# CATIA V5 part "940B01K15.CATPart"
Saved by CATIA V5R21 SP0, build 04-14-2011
Part number: 940B01K15
Bounding box of the stored display mesh (mm): x -8.5 to 406.7, y -7 to 7, z -25.901 to 9.099
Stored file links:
  C:\Users\ALI OZGUN\Desktop\alhan\940B01K15.CATPart
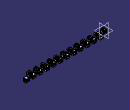
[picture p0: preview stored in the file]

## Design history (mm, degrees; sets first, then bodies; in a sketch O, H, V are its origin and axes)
Body1 (main body)
  Sketch1 on zx-plane, origin (0, 0, 0), H (-1, 0, 0), V (0, 0, 1)
    point P1 (-8.5, -8.9006)
    line L1 (-8.5, -7.9006) -> (-8, -7.4006)
    point P2 (-8, -7.4006)
    line L2 (-8, -7.4006) -> (-8, 6.6246)
    point P3 (-8, 6.6246)
    line L3 (-8, 6.6246) -> (-5.5251, 9.0994)
    point P4 (-5.5251, 9.0994)
    line L4 (-5.5251, 9.0994) -> (0, 9.0994)
    point P5 (0, 9.0994)
    line L5 (-8.5, -7.9006) -> (-8.5, -11.9006)
    point P6 (-8.5, -11.9006)
    line L6 (-8.5, -11.9006) -> (-5, -8.4006)
    point P7 (-3.5, -6.9006)
    line L7 (-5, -6.9006) -> (0, -6.9006)
    point P8 (0, -6.9006)
    line L8 (0, 6.2994) -> (-4.0825, 6.2994)
    point P9 (-4.0825, 6.2994)
    line L9 (-4.0825, 6.2994) -> (-5.2, 5.1819)
    point P10 (-5.2, 5.1819)
    line L10 (-5.2, 5.1819) -> (-5.2, -3.4006)
    point P11 (-5.2, -3.4006)
    line L11 (-5.2, -3.4006) -> (0, -3.4006)
    point P12 (0, -3.4006)
    point P13 (-8.5, -7.9006)
    point P14 (8, -7.4006)
    point P15 (8.5, -7.9006)
    line L12 (8.5, -7.9006) -> (8, -7.4006)
    point P16 (8, 6.6246)
    line L13 (8, -7.4006) -> (8, 6.6246)
    point P17 (5.5251, 9.0994)
    line L14 (8, 6.6246) -> (5.5251, 9.0994)
    point P18 (8.5, -11.9006)
    line L15 (8.5, -7.9006) -> (8.5, -11.9006)
    point P19 (3.5, -6.9006)
    line L16 (8.5, -11.9006) -> (5, -8.4006)
    point P20 (5.2, 5.1819)
    point P21 (4.0825, 6.2994)
    line L17 (4.0825, 6.2994) -> (5.2, 5.1819)
    point P22 (5.2, -3.4006)
    line L18 (5.2, 5.1819) -> (5.2, -3.4006)
    point P23 (0, -6.9006)
    line L19 (5, -6.9006) -> (0, -6.9006)
    point P24 (0, -3.4006)
    line L20 (5.2, -3.4006) -> (0, -3.4006)
    line L21 (0, 6.2994) -> (4.0825, 6.2994)
    point P25 (0, 9.0994)
    line L22 (5.5251, 9.0994) -> (0, 9.0994)
    point P26 (0, 6.2994)
    point P27 (0, 6.2994)
    line L23 (-5, -6.9006) -> (-5, -8.4006)
    line L24 (5, -6.9006) -> (5, -8.4006)
    distance L2 V = 8
    angle L3 L2 = 135
    distance L4 H = 9.0994
    distance L8 L4 = 2.8
    distance L10 L2 = 2.8
    distance L11 L7 = 3.5
    distance L9 L3 = 3
    length L3 = 3.5
    distance L4 L7 = 16
    distance L4 P6 = 21
    distance L5 L2 = 0.5
    length L5 = 4
    distance L23 L2 = 3
    vertical: L2 V, L5 V, L10 V, L23 V
    parallelism: L3 L1, L6 L1
    horizontal: L4 H, L7 H, L8 H, L11 H
    coincidence: P5 V, P8 V, P12 V, P1 L5, P26 V, P27 V, P5 P25, P8 P23, P12 P24, P26 P27, P7 L7, P7 L6, P19 L16, P19 L19
    symmetry: P2 P14 V, P13 P15 V, L1 L12 V, P3 P16 V, L2 L13 V, P4 P17 V, L3 L14 V, P6 P18 V, L5 L15 V, P7 P19 V, L6 L16 V, P10 P20 V, P9 P21 V, L9 L17 V, P11 P22 V, L10 L18 V, P8 P23 V, L7 L19 V, P12 P24 V, L11 L20 V, L8 L21 V, P5 P25 V, L4 L22 V, L23 L24 V
  Pad1: profile Sketch1, direction (0, 1, 0), length 7, mirrored extent
  Fillet1: radius 3, on edge [face of Pad1 from Sketch1.L22 | face of Pad1 from Sketch1.L14]; edge [face of Pad1 from Sketch1.L3 | face of Pad1 from Sketch1.L4]; edge [face of Pad1 from Sketch1.L2 | face of Pad1 from Sketch1.L3]; edge [face of Pad1 from Sketch1.L14 | face of Pad1 from Sketch1.L13]
  Fillet2: radius 1, on edge [face of Pad1 from Sketch1.L17 | face of Pad1 from Sketch1.L21]; edge [face of Pad1 from Sketch1.L18 | face of Pad1 from Sketch1.L17]; edge [face of Pad1 from Sketch1.L8 | face of Pad1 from Sketch1.L9]; edge [face of Pad1 from Sketch1.L9 | face of Pad1 from Sketch1.L10]
  Fillet3: radius 2, on edge [face of Pad1 from Sketch1.L23 | face of Pad1 from Sketch1.L6]; edge [face of Pad1 from Sketch1.L16 | face of Pad1 from Sketch1.L24]
  Fillet4: radius 1.5, on edge [face of Pad1 from Sketch1.L20 | face of Pad1 from Sketch1.L18]; edge [face of Pad1 from Sketch1.L10 | face of Pad1 from Sketch1.L11]
  Body2
    Sketch2 on zx-plane, origin (0, 0, 0), H (-1, 0, 0), V (0, 0, 1)
      line L1 (-8.5, -7.9006) -> (-10.5, -9.9006)
      line L2 (-10.5, -9.9006) -> (-17.3, -9.9006)
      line L3 (-8.5, -11.9006) -> (-9.05, -12.4506)
      line L4 (-9.05, -12.4506) -> (-9.05, -25.9006)
      line L5 (-9.05, -25.9006) -> (-17.3, -25.9006)
      line L6 (-17.3, -22.7006) -> (-11.85, -22.7006)
      line L7 (-11.85, -22.7006) -> (-11.85, -13.1006)
      line L8 (-11.85, -13.1006) -> (-17.3, -13.1006)
      axis line L9 (-17.3, -4.8689) -> (-17.3, -27.5881)
      point P6 (-17.3, -9.9006)
      point P7 (-17.3, -13.1006)
      point P8 (-17.3, -22.7006)
      point P9 (-17.3, -25.9006)
      reference projected line E1 (0, 9.0994) -> (-5.5251, 9.0994) from edge [face of Pad1 from Sketch1.L4 | end face of Pad1]
      reference projected line E2 (-8.5, -11.9006) -> (-5, -8.4006) from edge [face of Pad1 from Sketch1.L6 | end face of Pad1]
      reference projected line E3 (-8, -7.4006) -> (-8.5, -7.9006) from edge [face of Pad1 from Sketch1.L1 | end face of Pad1]
      projected line E4 (-8.5, -7.9006) -> (-8.5, -11.9006) from edge [face of Pad1 from Sketch1.L5 | end face of Pad1]
      projected line E5 (-8.5, -7.9006) -> (-8.5, -11.9006) from edge [face of Pad1 from Sketch1.L5 | end face of Pad1]
      reference projected line E6 (-8, 6.6246) -> (-8, -7.4006) from edge [face of Pad1 from Sketch1.L2 | end face of Pad1]
      line L10 (-17.3, -9.9006) -> (-17.3, -13.1006)
      line L11 (-17.3, -22.7006) -> (-17.3, -25.9006)
      distance L5 E1 = 35
      distance L2 L5 = 16
      distance L8 L2 = 3.2
      distance L6 L5 = 3.2
      distance L7 L4 = 2.8
      distance L4 E6 = 1.05
      distance L4 L9 = 8.25
      horizontal: L2 H, L5 H, L6 H, L8 H
      vertical: L4 V, L7 V, L9 V, L10 V, L11 V
      coincidence: P6 L9, P7 L9, P8 L9, P9 L9, L3 E2, L1 E3
    Pad2: profile Sketch2, direction (0, 1, 0), length 7, mirrored extent
    Mirror1: of the body so far, about face of Pad2 from Sketch2.L10
    Fillet5: radius 1.5, on edge [face of Pad2 | face of Mirror1] (x2); edge [face of Pad2 from Sketch2.L4 | face of Pad2]; edge [face of Mirror1 | face of Pad2] (x2); edge [face of Pad2 | face of Pad2 from Sketch2.L1]; edge [face of Pad2 from Sketch2.L7 | face of Pad2]; edge [face of Pad2 | face of Pad2 from Sketch2.L7]
  Add1: tool Body2
  RemoveFace1: RemoveFaces (face of Fillet5; face of Fillet1; face of Fillet5; face of Fillet1)
  Thickness1: Face (face of Pad2 from Sketch2.L4; face of Mirror1; face of Pad1 from Sketch1.L2; face of Pad1 from Sketch1.L13), Thickness 0.5
  RectPattern1: of the body so far, direction 1 instances 12, spacing 34.6, along edge [face of Pad1 | face of Pad2]
  Sketch3 on yz-plane, origin (0, 0, 0), H (0, 1, 0), V (0, 0, 1)
    construction line L1 (0, 4.5994) -> (0, -1.4006)
    point P1 (0, 4.5994)
    line L2 (2.5, 4.5994) -> (2.5, -1.4006)
    line L3 (-2.5, -1.4006) -> (-2.5, 4.5994)
    arc A1 centre (0, -1.4006) radius 2.5 from (2.5, -1.4006) to (-2.5, -1.4006) cw
    arc A2 centre (0, 4.5994) radius 2.5 from (-2.5, 4.5994) to (2.5, 4.5994) cw
    construction line L4 (0, -14.8006) -> (0, -20.8006)
    point P7 (0, -14.8006)
    point P8 (0, -20.8006)
    line L5 (2.5, -14.8006) -> (2.5, -20.8006)
    line L6 (-2.5, -20.8006) -> (-2.5, -14.8006)
    arc A3 centre (0, -20.8006) radius 2.5 from (2.5, -20.8006) to (-2.5, -20.8006) cw
    arc A4 centre (0, -14.8006) radius 2.5 from (-2.5, -14.8006) to (2.5, -14.8006) cw
    reference projected line E1 (-7, 9.0994) -> (7, 9.0994) from edge [face of Pad1 from Sketch1.L22 | face of Fillet1]
    distance L1 L2 = 2.5
    distance L4 L5 = 2.5
    length L1 = 6
    length L4 = 6
    distance A2 E1 = 2
    distance P8 P1 = 25.4
    coincidence: P1 V, P7 V
    vertical: L1 V, L4 V
    tangency: A1 L2, A2 L2, A1 L3, A2 L3, A3 L5, A4 L5, A3 L6, A4 L6
  Pocket1: profile Sketch3, direction (-1, 0, 0), through (limit type 3), opposite side through (limit type 3)
Body3
  Solid1: linked copy from another document
  Translate1: Direction xy-plane, Length 19.4, ToTransfor Solid1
